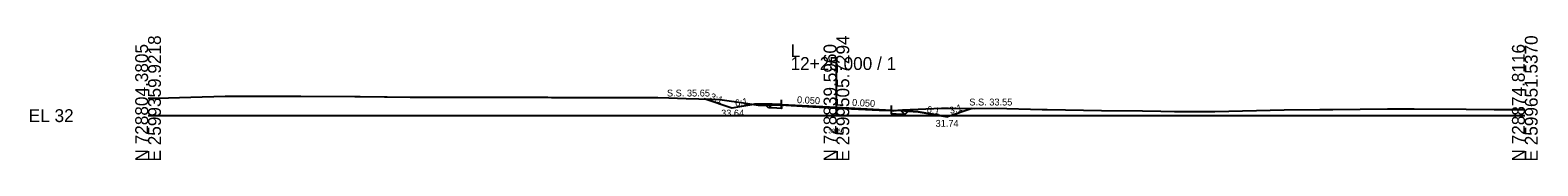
# Model space of a CAD drawing. Extents: x -26 to 3303, y -10 to 9555.
# Drawn here: x -25.7 to 302.8, y 4490.3 to 4517.4 of the extents above; entities that cross this region are included whole.
import ezdxf

# ---------------------------------------------------------------- set-up
doc = ezdxf.new("R2010")
doc.units = 0
for name, color, linetype in [('Exist Cross Section Cell', 7, 'Continuous'), ('Exist XS Center Line Elevation Label', 7, 'Continuous'), ('Exist XS Ground Line', 7, 'Continuous'), ('Prop XS Ditch Slope Text', 7, 'Continuous'), ('Prop XS Ditch Standard Text', 7, 'Continuous'), ('Prop XS Dump Level', 7, 'Continuous'), ('Prop XS Earthwork Shape', 7, 'Continuous'), ('Prop XS EOT Tick Mark', 7, 'Continuous'), ('Prop XS Finish Grade', 7, 'Continuous'), ('Prop XS Finish Grade Earthwork', 7, 'Continuous'), ('Prop XS Finish Grade Paved Shoulder', 7, 'Continuous'), ('Prop XS Finish Grade Pavement', 7, 'Continuous'), ('Prop XS Pvmt Edge Slope', 7, 'Continuous'), ('Prop XS SE Text', 7, 'Continuous'), ('Prop XS Side Slope Text', 7, 'Continuous'), ('Prop XS SS Elevation Text', 7, 'Continuous'), ('Prop XS Subgrade Earthwork', 7, 'Continuous')]:
    doc.layers.add(name, color=color, linetype=linetype)

msp = doc.modelspace()

# ---------------------------------------------------------------- linework, layer by layer
at = {"layer": 'Exist Cross Section Cell'}
for p, q in [((150, 4500), (150, 4512.75)), ((0, 4500), (150, 4500)), ((150, 4500), (300, 4500))]:
    msp.add_line(p, q, dxfattribs=at)
at = {"layer": 'Exist XS Ground Line'}
msp.add_lwpolyline([(0, 4503.79), (1.95, 4503.8), (9.31, 4504.02), (16.83, 4504.25), (17.53, 4504.24), (33.3, 4504.21), (45.02, 4504.19), (46.24, 4504.16), (51.51, 4504.06), (52.1, 4504.06), (57.12, 4504.05), (75.89, 4504.01), (86.39, 4503.99), (87.1, 4503.99), (87.9, 4503.97), (111.07, 4503.95), (113.51, 4503.89), (117.22, 4503.76), (120.05, 4503.68), (124.62, 4503.54), (130.29, 4502.7), (132.95, 4502.29), (134.6, 4502.3), (137.8, 4502.33), (144.84, 4501.95), (150.29, 4501.62), (159.28, 4501.22), (162.37, 4501.11), (164.41, 4501.26), (172.9, 4501.59), (174.44, 4501.64), (180.09, 4501.55), (184.57, 4501.61), (194.84, 4501.36), (195.89, 4501.33), (199.91, 4501.26), (207.74, 4501.14), (216.66, 4501.01), (220.72, 4500.97), (223.63, 4500.91), (232.48, 4500.89), (247.54, 4501.28), (255.37, 4501.31), (258.2, 4501.3), (270.1, 4501.46), (273.2, 4501.49), (275.89, 4501.48), (287.24, 4501.39), (293.31, 4501.34), (300, 4501.37)], dxfattribs=at)
at = {"layer": 'Prop XS Dump Level'}
for p, q in [((138, 4502.41), (150, 4501.81)), ((150, 4501.81), (162, 4501.21))]:
    msp.add_line(p, q, dxfattribs=at)
at = {"layer": 'Prop XS Earthwork Shape'}
for points in [[(121.17, 4503.65), (124.62, 4503.54), (130.29, 4502.7), (132, 4502.44), (127.2, 4501.64)], [(121.17, 4503.65), (124.62, 4503.54), (130.29, 4502.7), (132, 4502.44), (127.2, 4501.64)], [(132, 4502.44), (132.95, 4502.29), (134.6, 4502.3), (134.63, 4502.3), (134.43, 4502.49), (132.21, 4502.47)], [(132, 4502.44), (132.95, 4502.29), (134.6, 4502.3), (134.63, 4502.3), (134.43, 4502.49), (132.21, 4502.47)], [(135.21, 4501.72), (134.63, 4502.3), (137.8, 4502.33), (138, 4502.32), (138, 4501.58), (136, 4501.68)], [(135.21, 4501.72), (134.63, 4502.3), (137.8, 4502.33), (138, 4502.32), (138, 4501.58), (136, 4501.68)], [(162, 4501.12), (162.37, 4501.11), (164.41, 4501.26), (172.9, 4501.59), (174.44, 4501.64), (179.61, 4501.55), (174.18, 4499.74), (167.81, 4500.8), (165.62, 4500.98), (164.88, 4500.23), (164, 4500.28), (162, 4500.38)], [(162, 4501.12), (162.37, 4501.11), (164.41, 4501.26), (172.9, 4501.59), (174.44, 4501.64), (179.61, 4501.55), (174.18, 4499.74), (167.81, 4500.8), (165.62, 4500.98), (164.88, 4500.23), (164, 4500.28), (162, 4500.38)]]:
    msp.add_lwpolyline(points, close=True, dxfattribs=at)
at = {"layer": 'Prop XS EOT Tick Mark'}
for p, q in [((138, 4502.41), (138, 4503.41)), ((162, 4501.21), (162, 4502.21))]:
    msp.add_line(p, q, dxfattribs=at)
at = {"layer": 'Prop XS Finish Grade'}
for p, q in [((136, 4502.51), (134.43, 4502.49)), ((164, 4501.11), (165.62, 4500.98))]:
    msp.add_line(p, q, dxfattribs=at)
at = {"layer": 'Prop XS Finish Grade Earthwork'}
for p, q in [((127.2, 4501.64), (121.17, 4503.65)), ((132.21, 4502.47), (127.2, 4501.64)), ((134.43, 4502.49), (132.21, 4502.47)), ((165.62, 4500.98), (167.81, 4500.8)), ((179.61, 4501.55), (174.18, 4499.74)), ((167.81, 4500.8), (174.18, 4499.74))]:
    msp.add_line(p, q, dxfattribs=at)
at = {"layer": 'Prop XS Finish Grade Paved Shoulder'}
for p, q in [((138, 4502.41), (136, 4502.51)), ((162, 4501.21), (164, 4501.11))]:
    msp.add_line(p, q, dxfattribs=at)
at = {"layer": 'Prop XS Finish Grade Pavement'}
for p, q in [((138, 4502.41), (150, 4501.81)), ((150, 4501.81), (162, 4501.21))]:
    msp.add_line(p, q, dxfattribs=at)
at = {"layer": 'Prop XS Pvmt Edge Slope'}
for p, q in [((135.21, 4501.72), (134.43, 4502.49)), ((136, 4502.51), (135.21, 4501.72)), ((164, 4501.11), (164.88, 4500.23)), ((164.88, 4500.23), (165.62, 4500.98))]:
    msp.add_line(p, q, dxfattribs=at)
at = {"layer": 'Prop XS Subgrade Earthwork'}
for p, q in [((135.21, 4501.72), (134.43, 4502.49)), ((136, 4501.68), (135.21, 4501.72)), ((138, 4501.58), (136, 4501.68)), ((138, 4501.58), (138, 4502.32)), ((162, 4500.38), (162, 4501.12)), ((164.88, 4500.23), (165.62, 4500.98)), ((162, 4500.38), (164, 4500.28)), ((164, 4500.28), (164.88, 4500.23))]:
    msp.add_line(p, q, dxfattribs=at)

# ---------------------------------------------------------------- texts
at = {"layer": 'Exist Cross Section Cell'}
for s, p in [('E 2599505.7294', (152.8, 4490)), ('E 2599651.5370', (302.8, 4490)), ('N 728804.3805', (0, 4490)), ('E 2599359.9218', (2.8, 4490)), ('N 728839.5960', (150, 4490)), ('N 728874.8116', (300, 4490))]:
    msp.add_text(s, height=2.8, rotation=90, dxfattribs=at).set_placement(p)
for s, p in [('L', (140, 4512.75)), ('12+25.000 / 1', (140, 4509.95)), ('EL 32', (-26, 4498.6))]:
    msp.add_text(s, height=2.8, dxfattribs=at).set_placement(p)
at = {"layer": 'Exist XS Center Line Elevation Label'}
msp.add_text('33.64', height=1, dxfattribs=at).set_placement((148.26, 4496.14))
at = {"layer": 'Prop XS Ditch Slope Text'}
for rotation, p in [(9.4623, (128.02, 4501.95)), (350.5377, (169.61, 4500.67))]:
    msp.add_text('6:1', height=1.5, rotation=rotation, dxfattribs=at).set_placement(p)
at = {"layer": 'Prop XS Ditch Standard Text'}
for s, p in [('33.64', (124.87, 4499.79)), ('31.74', (171.61, 4497.57))]:
    msp.add_text(s, height=1.5, dxfattribs=at).set_placement(p)
at = {"layer": 'Prop XS Dump Level'}
for s, height, p in [('Case1', 0.04, (130, 4502.41)), ('Eop', 0.3, (137.8, 4502.03)), ('Eop', 0.3, (162.37, 4500.81)), ('Case1', 0.04, (170, 4500.59))]:
    msp.add_text(s, height=height, dxfattribs=at).set_placement(p)
at = {"layer": 'Prop XS SE Text'}
for p in [(141.38, 4502.74), (153.38, 4502.14)]:
    msp.add_text('0.050', height=1.5, rotation=357.1376, dxfattribs=at).set_placement(p)
at = {"layer": 'Prop XS Side Slope Text'}
for rotation, p in [(338.321, (122.31, 4503.59)), (16.5137, (174.85, 4500.33))]:
    msp.add_text('3:1', height=1.5, rotation=rotation, dxfattribs=at).set_placement(p)
at = {"layer": 'Prop XS SS Elevation Text'}
for s, p in [('S.S. 35.65', (113.07, 4504.17)), ('S.S. 33.55', (178.96, 4502.21))]:
    msp.add_text(s, height=1.5, dxfattribs=at).set_placement(p)

doc.saveas('drawing.dxf')
